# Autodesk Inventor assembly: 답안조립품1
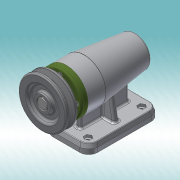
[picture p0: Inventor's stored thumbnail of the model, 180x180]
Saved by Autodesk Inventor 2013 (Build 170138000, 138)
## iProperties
Created: 2017-01
Part Number: 답안조립품1
Document SubType Name: Assembly
Designer: dgall
Author: dgall
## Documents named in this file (12)
- C:\Users\dgall\Desktop\470107V1009\답안조립품1.iam
- C:\Users\dgall\Desktop\470107V1009\V벨트풀리.ipt
- C:\Users\dgall\Desktop\470107V1009\멈춤나사 M3x8.ipt
- C:\Users\dgall\Desktop\470107V1009\베어링 6004.ipt
- C:\Users\dgall\Desktop\470107V1009\베어링 51202.ipt
- C:\Users\dgall\Desktop\470107V1009\본체.ipt
- C:\Users\dgall\Desktop\470107V1009\볼트 M4 x 12.ipt
- C:\Users\dgall\Desktop\470107V1009\어댑터슬리브.ipt
- C:\Users\dgall\Desktop\470107V1009\오일 실.ipt
- C:\Users\dgall\Desktop\470107V1009\축.ipt
- C:\Users\dgall\Desktop\470107V1009\커버.ipt
- C:\Users\dgall\Desktop\470107V1009\키 5 x 5 x 16.ipt
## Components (6 placed, 2 different names)
1. V벨트풀리:1
2. ISO 4762 M4 x 12:1
3. ISO 4762 M4 x 12:2
4. ISO 4762 M4 x 12:3
5. ISO 4762 M4 x 12:4
6. ISO 4762 M4 x 12:5
